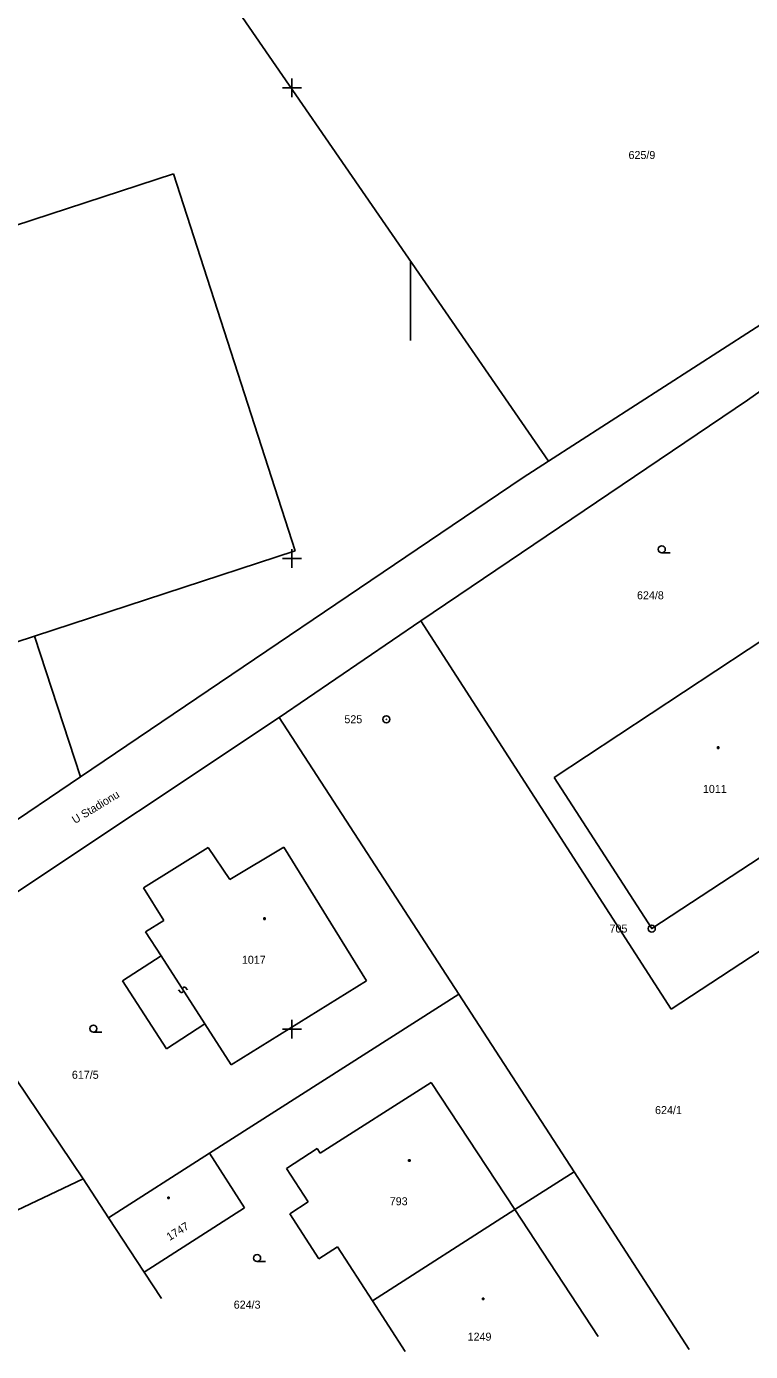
# Model space of a CAD drawing. Extents: x -493352 to -492964, y -1127001 to -1126712.
# Drawn here: x -493096.9 to -493050.8, y -1127000.5 to -1126916.1 of the extents above; entities that cross this region are included whole.
import ezdxf

# ---------------------------------------------------------------- set-up
doc = ezdxf.new("R2010")
doc.units = 0
doc.layers.add('katastrální mapa', color=7, linetype='Continuous')
doc.layers.add('síť', color=7, linetype='Continuous')

msp = doc.modelspace()

# ---------------------------------------------------------------- linework, layer by layer
at = {"layer": 'katastrální mapa'}
for p, q in [((-493063.66, -1126943.8), (-493007.98, -1126907.88)), ((-493083.58, -1126914.91), (-493063.66, -1126943.8)), ((-493104.21, -1126930.93), (-493087.54, -1126925.49)), ((-493087.54, -1126925.49), (-493079.8, -1126949.52)), ((-493072.44, -1126936.11), (-493072.44, -1126931.11)), ((-493050.98, -1126939.91), (-493048.54, -1126938.17)), ((-493071.8, -1126953.97), (-493050.98, -1126939.91)), ((-493065.33, -1126944.88), (-493063.66, -1126943.8)), ((-493093.48, -1126963.92), (-493065.33, -1126944.88)), ((-493096.4, -1126954.95), (-493079.8, -1126949.52)), ((-493056.44, -1126949.64), (-493055.91, -1126949.64)), ((-493080.81, -1126960.14), (-493071.8, -1126953.97)), ((-493071.8, -1126953.97), (-493055.85, -1126978.73)), ((-493063.3, -1126963.95), (-493048.88, -1126954.44)), ((-493125.98, -1126964.63), (-493096.4, -1126954.95)), ((-493096.4, -1126954.95), (-493093.48, -1126963.92)), ((-493103.07, -1126974.96), (-493080.81, -1126960.14)), ((-493080.81, -1126960.14), (-493069.38, -1126977.76)), ((-493052.89, -1126962.01), (-493052.8, -1126962.01)), ((-493052.89, -1126962.1), (-493052.89, -1126962.01)), ((-493052.8, -1126962.1), (-493052.89, -1126962.1)), ((-493052.8, -1126962.01), (-493052.8, -1126962.1)), ((-493134.85, -1126991.91), (-493093.48, -1126963.92)), ((-493063.3, -1126963.95), (-493057.08, -1126973.59)), ((-493057.08, -1126973.59), (-493042.57, -1126964.05)), ((-493055.85, -1126978.73), (-493034.83, -1126964.91)), ((-493089.45, -1126970.98), (-493085.34, -1126968.42)), ((-493085.34, -1126968.42), (-493083.96, -1126970.46)), ((-493083.96, -1126970.46), (-493080.52, -1126968.4)), ((-493080.52, -1126968.4), (-493075.25, -1126976.92)), ((-493089.45, -1126970.98), (-493088.16, -1126973.07)), ((-493089.33, -1126973.79), (-493088.16, -1126973.07)), ((-493081.79, -1126972.91), (-493081.7, -1126972.91)), ((-493081.79, -1126973), (-493081.79, -1126972.91)), ((-493081.7, -1126973), (-493081.79, -1126973)), ((-493081.7, -1126972.91), (-493081.7, -1126973)), ((-493089.33, -1126973.79), (-493088.34, -1126975.33)), ((-493090.8, -1126976.91), (-493088.34, -1126975.33)), ((-493088.34, -1126975.33), (-493085.55, -1126979.65)), ((-493090.8, -1126976.91), (-493088, -1126981.24)), ((-493087.09, -1126977.65), (-493087.23, -1126977.49)), ((-493086.94, -1126977.56), (-493086.96, -1126977.64)), ((-493086.93, -1126977.34), (-493086.95, -1126977.42)), ((-493086.95, -1126977.42), (-493086.94, -1126977.56)), ((-493086.88, -1126977.31), (-493086.93, -1126977.34)), ((-493086.8, -1126977.33), (-493086.88, -1126977.31)), ((-493086.66, -1126977.49), (-493086.8, -1126977.33)), ((-493083.87, -1126982.26), (-493075.25, -1126976.92)), ((-493087.01, -1126977.67), (-493087.09, -1126977.65)), ((-493086.96, -1126977.64), (-493087.01, -1126977.67)), ((-493085.25, -1126987.91), (-493069.38, -1126977.76)), ((-493069.38, -1126977.76), (-493062.03, -1126989.09)), ((-493088, -1126981.24), (-493085.55, -1126979.65)), ((-493085.55, -1126979.65), (-493083.87, -1126982.26)), ((-493092.65, -1126980.19), (-493092.12, -1126980.19)), ((-493098.33, -1126982.06), (-493093.31, -1126989.53)), ((-493078.21, -1126987.89), (-493071.13, -1126983.39)), ((-493071.13, -1126983.39), (-493065.8, -1126991.5)), ((-493080.34, -1126988.88), (-493078.39, -1126987.61)), ((-493078.39, -1126987.61), (-493078.21, -1126987.89)), ((-493091.69, -1126992.03), (-493085.25, -1126987.91)), ((-493085.25, -1126987.91), (-493083.02, -1126991.39)), ((-493072.57, -1126988.32), (-493072.48, -1126988.32)), ((-493072.57, -1126988.41), (-493072.57, -1126988.32)), ((-493072.48, -1126988.41), (-493072.57, -1126988.41)), ((-493072.48, -1126988.32), (-493072.48, -1126988.41)), ((-493080.34, -1126988.88), (-493078.97, -1126991)), ((-493065.8, -1126991.5), (-493062.03, -1126989.09)), ((-493062.03, -1126989.09), (-493054.69, -1127000.42)), ((-493114.79, -1126999.77), (-493093.31, -1126989.53)), ((-493093.31, -1126989.53), (-493091.69, -1126992.03)), ((-493087.91, -1126990.7), (-493087.82, -1126990.7)), ((-493087.91, -1126990.79), (-493087.91, -1126990.7)), ((-493087.82, -1126990.79), (-493087.91, -1126990.79)), ((-493087.82, -1126990.7), (-493087.82, -1126990.79)), ((-493080.14, -1126991.76), (-493078.97, -1126991)), ((-493089.42, -1126995.48), (-493083.02, -1126991.39)), ((-493080.14, -1126991.76), (-493078.28, -1126994.64)), ((-493074.88, -1126997.31), (-493065.8, -1126991.5)), ((-493065.8, -1126991.5), (-493060.5, -1126999.59)), ((-493091.69, -1126992.03), (-493089.42, -1126995.48)), ((-493078.28, -1126994.64), (-493077.1, -1126993.87)), ((-493077.1, -1126993.87), (-493074.88, -1126997.31)), ((-493082.22, -1126994.81), (-493081.69, -1126994.81)), ((-493089.42, -1126995.48), (-493088.31, -1126997.17)), ((-493074.88, -1126997.31), (-493072.78, -1127000.54)), ((-493067.86, -1126997.14), (-493067.77, -1126997.14)), ((-493067.86, -1126997.23), (-493067.86, -1126997.14)), ((-493067.77, -1126997.23), (-493067.86, -1126997.23)), ((-493067.77, -1126997.14), (-493067.77, -1126997.23))]:
    msp.add_line(p, q, dxfattribs=at)
for centre, radius in [((-493056.44, -1126949.415), 0.225), ((-493073.99, -1126960.25), 0.225), ((-493073.99, -1126960.25), 0.003), ((-493057.08, -1126973.59), 0.225), ((-493057.08, -1126973.59), 0.003), ((-493092.65, -1126979.965), 0.225), ((-493082.22, -1126994.585), 0.225)]:
    msp.add_circle(centre, radius, dxfattribs=at)
at = {"layer": 'síť'}
for p, q in [((-493080.6, -1126920), (-493079.4, -1126920)), ((-493080, -1126919.4), (-493080, -1126920.6)), ((-493080, -1126949.4), (-493080, -1126950.6)), ((-493080.6, -1126950), (-493079.4, -1126950)), ((-493080.6, -1126980), (-493079.4, -1126980)), ((-493080, -1126979.4), (-493080, -1126980.6))]:
    msp.add_line(p, q, dxfattribs=at)

# ---------------------------------------------------------------- texts
at = {"layer": 'katastrální mapa'}
for s, p in [('625/9', (-493058.56, -1126924.54)), ('624/8', (-493058.02, -1126952.6)), ('525', (-493076.66, -1126960.5)), ('1011', (-493053.82, -1126964.94)), ('705', (-493059.77, -1126973.84)), ('1017', (-493083.19, -1126975.83)), ('617/5', (-493094.02, -1126983.16)), ('624/1', (-493056.87, -1126985.41)), ('793', (-493073.77, -1126991.22)), ('624/3', (-493083.71, -1126997.81)), ('1249', (-493068.81, -1126999.85))]:
    msp.add_text(s, height=0.51, dxfattribs=at).set_placement(p)
for s, rotation, p in [('U Stadionu', 31.30803, (-493093.82, -1126966.93)), ('1747', 32.256, (-493087.79, -1126993.5))]:
    msp.add_text(s, height=0.51, rotation=rotation, dxfattribs=at).set_placement(p)

doc.saveas('drawing.dxf')
